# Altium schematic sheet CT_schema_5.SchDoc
size 274 x 160 mm
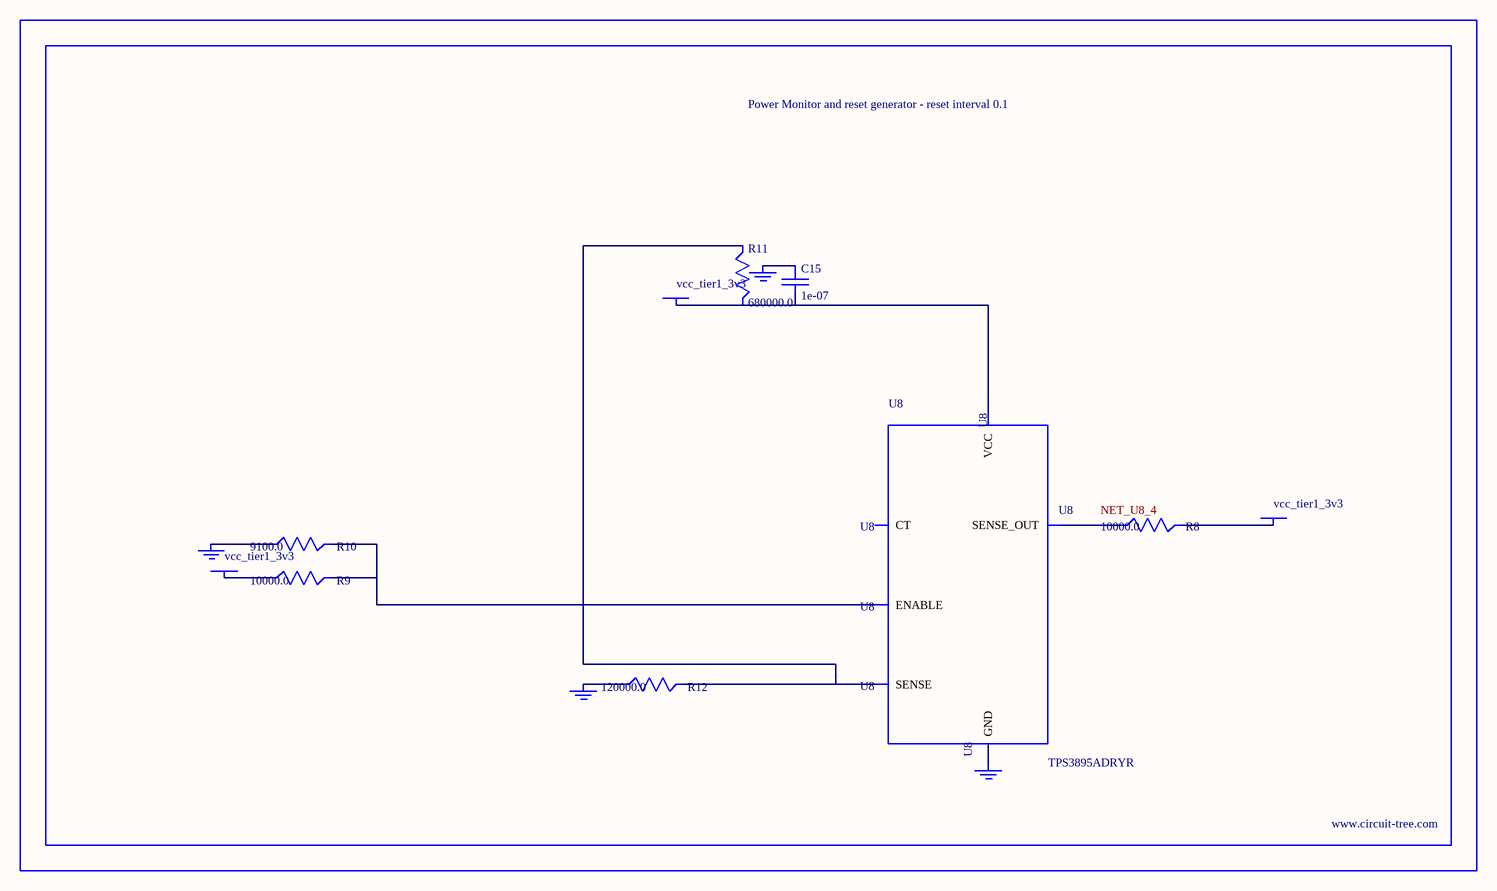
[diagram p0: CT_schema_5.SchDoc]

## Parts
BORDER4  (no value)
C15  1e-07  [C0402]
GND_INSTANCE_4_0  (no value)
GND_INSTANCE_4_1  (no value)
GND_INSTANCE_4_2  (no value)
GND_INSTANCE_4_3  (no value)
POWER_INSTANCE_4_0  vcc_tier1_3v3
POWER_INSTANCE_4_1  vcc_tier1_3v3
POWER_INSTANCE_4_2  vcc_tier1_3v3
R8  10000.0  [R0603]
R9  10000.0  [R0603]
R10  9100.0  [R0603]
R11  680000.0  [R0603]
R12  120000.0  [R0603]
U8  TPS3895ADRYR  [SON-6]

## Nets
NetC15_1: C15.1 GND_INSTANCE_4_2.0(GND)
NetC15_2: C15.2 POWER_INSTANCE_4_2.0(PWR) R11.2 U8.6(VCC)
NetGND_INSTANCE_4_0_0: GND_INSTANCE_4_0.0(GND) R10.1
NetGND_INSTANCE_4_1_0: GND_INSTANCE_4_1.0(GND) R12.1
NetGND_INSTANCE_4_3_0: GND_INSTANCE_4_3.0(GND) U8.2(GND)
NetPOWER_INSTANCE_4_0_0: POWER_INSTANCE_4_0.0(PWR) R9.1
NetPOWER_INSTANCE_4_1_0: POWER_INSTANCE_4_1.0(PWR) R8.2
NetR8_1: R8.1 U8.4(SENSE_OUT)
NetR9_2: R9.2 R10.2 U8.1(ENABLE)
NetR11_1: R11.1 R12.2 U8.3(SENSE)

Not connected (* = marked no-connect by the designer): U8 5(CT)

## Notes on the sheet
- Labels drawn without touching a wire or pin: NET_U8_4

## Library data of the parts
BORDER4 = BORDER_PAGE4
C15 = C0402C104K3RACTU
GND_INSTANCE_4_0-GND_INSTANCE_4_3 = GND
POWER_INSTANCE_4_0-POWER_INSTANCE_4_2 = PWR
R8 R9 = RC0603JR-0710KL
R10 = RC0603JR-079K1L
R11 = RC0603JR-07680KL
R12 = RC0603JR-07120KL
